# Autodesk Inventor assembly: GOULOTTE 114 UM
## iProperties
Shininess: 41.0
Angle Display Precision: 2
Document Length Units: 11269
Document Angle Units: 11279
Document Time Units: 11290
Document Mass Units: 11283
Document Length Units Precision: 3
Document Angle Units Precision: 2
Part Number: GOULOTTE 114 UM
Document SubType Name: Assembly
Density: 0.0
Volumn: 0.0
Area: 0.0
PropertySet Name: Model Information
Control State: 0
Master: False
Checked Out: False
